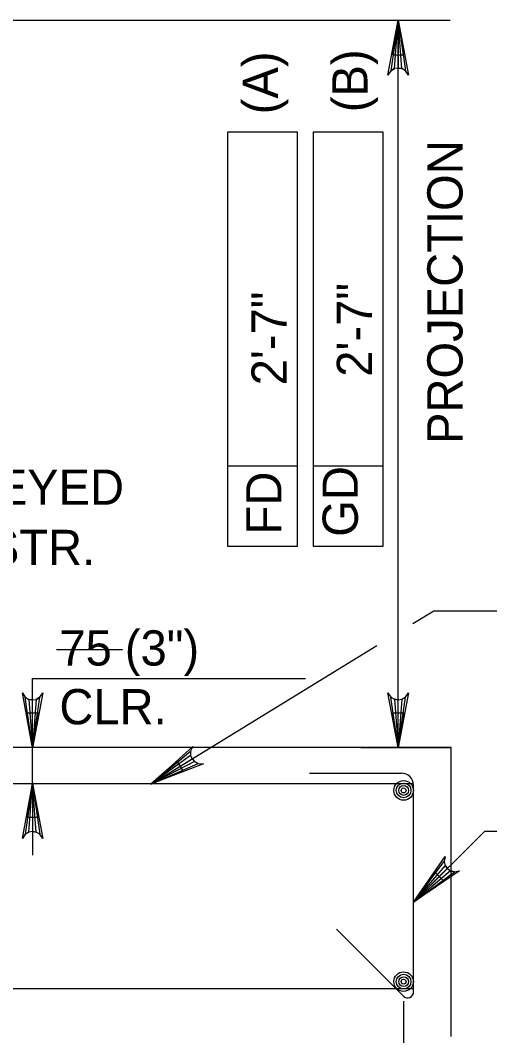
# Model space of a CAD drawing. Extents: x 179 to 454, y -271 to 54.
# Drawn here: x 273.414 to 275.014, y -52.571 to -49.113 of the extents above; entities that cross this region are included whole.
import ezdxf

# ---------------------------------------------------------------- set-up
doc = ezdxf.new("R2010")
doc.units = 0
for name, color, linetype in [('Level 3', 7, 'Continuous'), ('Level 4', 7, 'Continuous'), ('Level 41', 7, 'Continuous'), ('Level 5', 7, 'Continuous'), ('Level 6', 7, 'Continuous'), ('Level 9', 7, 'Continuous')]:
    doc.layers.add(name, color=color, linetype=linetype)

msp = doc.modelspace()

# ---------------------------------------------------------------- linework, layer by layer
at = {"layer": 'Level 4'}
for p, q in [((272.9268, -49.1131), (274.8793, -49.1131)), ((274.7022, -51.5902), (274.7022, -49.1132)), ((274.1223, -50.9053), (274.1223, -49.4933)), ((274.1223, -49.4933), (274.3586, -49.4933)), ((274.3586, -49.4933), (274.3586, -50.9053)), ((274.4138, -50.9053), (274.4138, -49.4933)), ((274.4138, -49.4933), (274.65, -49.4933)), ((274.65, -49.4933), (274.65, -50.9053)), ((274.3586, -50.6316), (274.1223, -50.6316)), ((274.65, -50.6316), (274.4138, -50.6316)), ((274.3586, -50.9053), (274.1223, -50.9053)), ((274.65, -50.9053), (274.4138, -50.9053)), ((274.7517, -51.1678), (274.8235, -51.1238)), ((274.8235, -51.1238), (276.258, -51.1238)), ((273.8612, -51.7132), (274.6294, -51.2427)), ((273.4565, -51.3543), (274.3867, -51.3543)), ((273.4565, -51.7132), (273.4565, -51.3543)), ((274.5752, -51.5902), (274.8793, -51.5902)), ((273.4565, -51.8389), (273.4565, -51.957)), ((274.7549, -52.117), (274.9982, -51.8745)), ((274.9982, -51.8745), (276.9407, -51.8745)), ((274.7208, -52.4539), (274.7208, -54.2843))]:
    msp.add_line(p, q, dxfattribs=at)
for points in [[(274.7022, -49.1132), (274.7372, -49.2996), (274.7272, -49.2852), (274.7147, -49.2778), (274.7022, -49.2757), (274.6898, -49.2778), (274.6773, -49.2852), (274.6673, -49.2996), (274.7022, -49.1132), (274.6773, -49.2852), (274.6898, -49.2778), (274.7022, -49.1132), (274.7022, -49.2757), (274.7147, -49.2778), (274.7022, -49.1132), (274.7272, -49.2852)], [(273.4565, -51.5905), (273.4216, -51.4041), (273.4315, -51.4184), (273.444, -51.4258), (273.4565, -51.428), (273.469, -51.4258), (273.4815, -51.4184), (273.4914, -51.4041), (273.4565, -51.5905), (273.4815, -51.4184), (273.469, -51.4258), (273.4565, -51.5905), (273.4565, -51.428), (273.444, -51.4258), (273.4565, -51.5905), (273.4315, -51.4184)], [(274.7022, -51.5902), (274.6673, -51.4037), (274.6773, -51.4181), (274.6898, -51.4255), (274.7022, -51.4277), (274.7147, -51.4255), (274.7272, -51.4181), (274.7372, -51.4037), (274.7022, -51.5902), (274.7272, -51.4181), (274.7147, -51.4255), (274.7022, -51.5902), (274.7022, -51.4277), (274.6898, -51.4255), (274.7022, -51.5902), (274.6773, -51.4181)], [(273.8612, -51.7132), (274.002, -51.5861), (273.9949, -51.6021), (273.9951, -51.6166), (273.9998, -51.6284), (274.0082, -51.6379), (274.021, -51.6447), (274.0385, -51.6457), (273.8612, -51.7132), (274.021, -51.6447), (274.0082, -51.6379), (273.8612, -51.7132), (273.9998, -51.6284), (273.9951, -51.6166), (273.8612, -51.7132), (273.9949, -51.6021)], [(273.4565, -51.7132), (273.4914, -51.8997), (273.4815, -51.8853), (273.469, -51.8779), (273.4565, -51.8757), (273.444, -51.8779), (273.4315, -51.8853), (273.4216, -51.8997), (273.4565, -51.7132), (273.4315, -51.8853), (273.444, -51.8779), (273.4565, -51.7132), (273.4565, -51.8757), (273.469, -51.8779), (273.4565, -51.7132), (273.4815, -51.8853)], [(274.7549, -52.117), (274.8623, -51.9607), (274.8591, -51.9778), (274.8627, -51.9919), (274.87, -52.0022), (274.8803, -52.0096), (274.8944, -52.0132), (274.9116, -52.0102), (274.7549, -52.117), (274.8944, -52.0132), (274.8803, -52.0096), (274.7549, -52.117), (274.87, -52.0022), (274.8627, -51.9919), (274.7549, -52.117), (274.8591, -51.9778)]]:
    msp.add_lwpolyline(points, dxfattribs=at)
for points in [[(274.6825, -49.2312), (274.7219, -49.2312), (274.7022, -49.1132)], [(273.4762, -51.4724), (273.4368, -51.4724), (273.4565, -51.5905)], [(274.6825, -51.4721), (274.7219, -51.4721), (274.7022, -51.5902)], [(273.9701, -51.6698), (273.9495, -51.6362), (273.8591, -51.7147)], [(273.4762, -51.8284), (273.4368, -51.8284), (273.4565, -51.7102)], [(274.8564, -52.0436), (274.8287, -52.0157), (274.7589, -52.113)]]:
    msp.add_lwpolyline(points, close=True, dxfattribs=at)
at = {"layer": 'Level 41'}
msp.add_line((273.5379, -51.2555), (273.7623, -51.2555), dxfattribs=at)
at = {"layer": 'Level 5'}
for p, q in [((274.7237, -51.5905), (274.7237, -51.5905)), ((274.874, -51.5905), (274.874, -51.5905))]:
    msp.add_line(p, q, dxfattribs=at)
at = {"layer": 'Level 6'}
for p, q in [((274.3997, -51.6774), (274.7139, -51.6774)), ((274.7546, -51.7132), (270.4414, -51.7132)), ((274.7549, -52.422), (274.7549, -51.7184)), ((274.4917, -52.2083), (274.7199, -52.4365)), ((270.4411, -52.4105), (274.7549, -52.4105))]:
    msp.add_line(p, q, dxfattribs=at)
for centre, radius in [((274.7208, -51.736), 0.0333), ((274.7208, -51.736), 0.025), ((274.7208, -51.736), 0.0167), ((274.7208, -51.736), 0.00833), ((274.7208, -52.3871), 0.0333), ((274.7208, -52.3871), 0.025), ((274.7208, -52.3871), 0.0167), ((274.7208, -52.3871), 0.00833)]:
    msp.add_circle(centre, radius, dxfattribs=at)
for centre, radius, start, end in [((274.7138, -51.7184), 0.041, 0, 90), ((274.7344, -52.422), 0.0205, 225, 0)]:
    msp.add_arc(centre, radius, start, end, dxfattribs=at)
at = {"layer": 'Level 9'}
for p, q in [((274.8834, -51.5902), (272.7378, -51.5902)), ((274.8834, -52.5744), (274.8834, -51.5902))]:
    msp.add_line(p, q, dxfattribs=at)

# ---------------------------------------------------------------- texts
at = {"layer": 'Level 3'}
for s, p in [('75 (3")', (273.5478, -51.3107)), ('CLR.', (273.5478, -51.5108))]:
    msp.add_text(s, height=0.12, dxfattribs=at).set_placement(p)
at = {"layer": 'Level 4'}
for s, p in [('(A)', (274.2922, -49.4332)), ('(B)', (274.5979, -49.4261)), ('PROJECTION', (274.9216, -50.556)), ('FD', (274.3043, -50.8642)), ('GD', (274.5648, -50.8721))]:
    msp.add_text(s, height=0.12, rotation=90, dxfattribs=at).set_placement(p)
for s, p in [('T/3 KEYED', (272.9475, -50.763)), ('CONSTR.', (272.9475, -50.9684))]:
    msp.add_text(s, height=0.12, dxfattribs=at).set_placement(p)
at = {"layer": 'Level 41'}
for p in [(274.6132, -50.3272), (274.3224, -50.3563)]:
    msp.add_text('2\'-7"', height=0.12, rotation=90, dxfattribs=at).set_placement(p)

doc.saveas('drawing.dxf')
